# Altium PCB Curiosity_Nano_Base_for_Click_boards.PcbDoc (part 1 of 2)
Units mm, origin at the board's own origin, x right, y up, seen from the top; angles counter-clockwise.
Board outline 74.93 x 107.95 mm, 4 copper layers (Top Layer, Internal Plane 1 Gnd, Internal Plane 2 Pwr, Bottom Layer), stack 1.565 mm thick; 66 components, 59 nets, 464 pads, 89 vias.
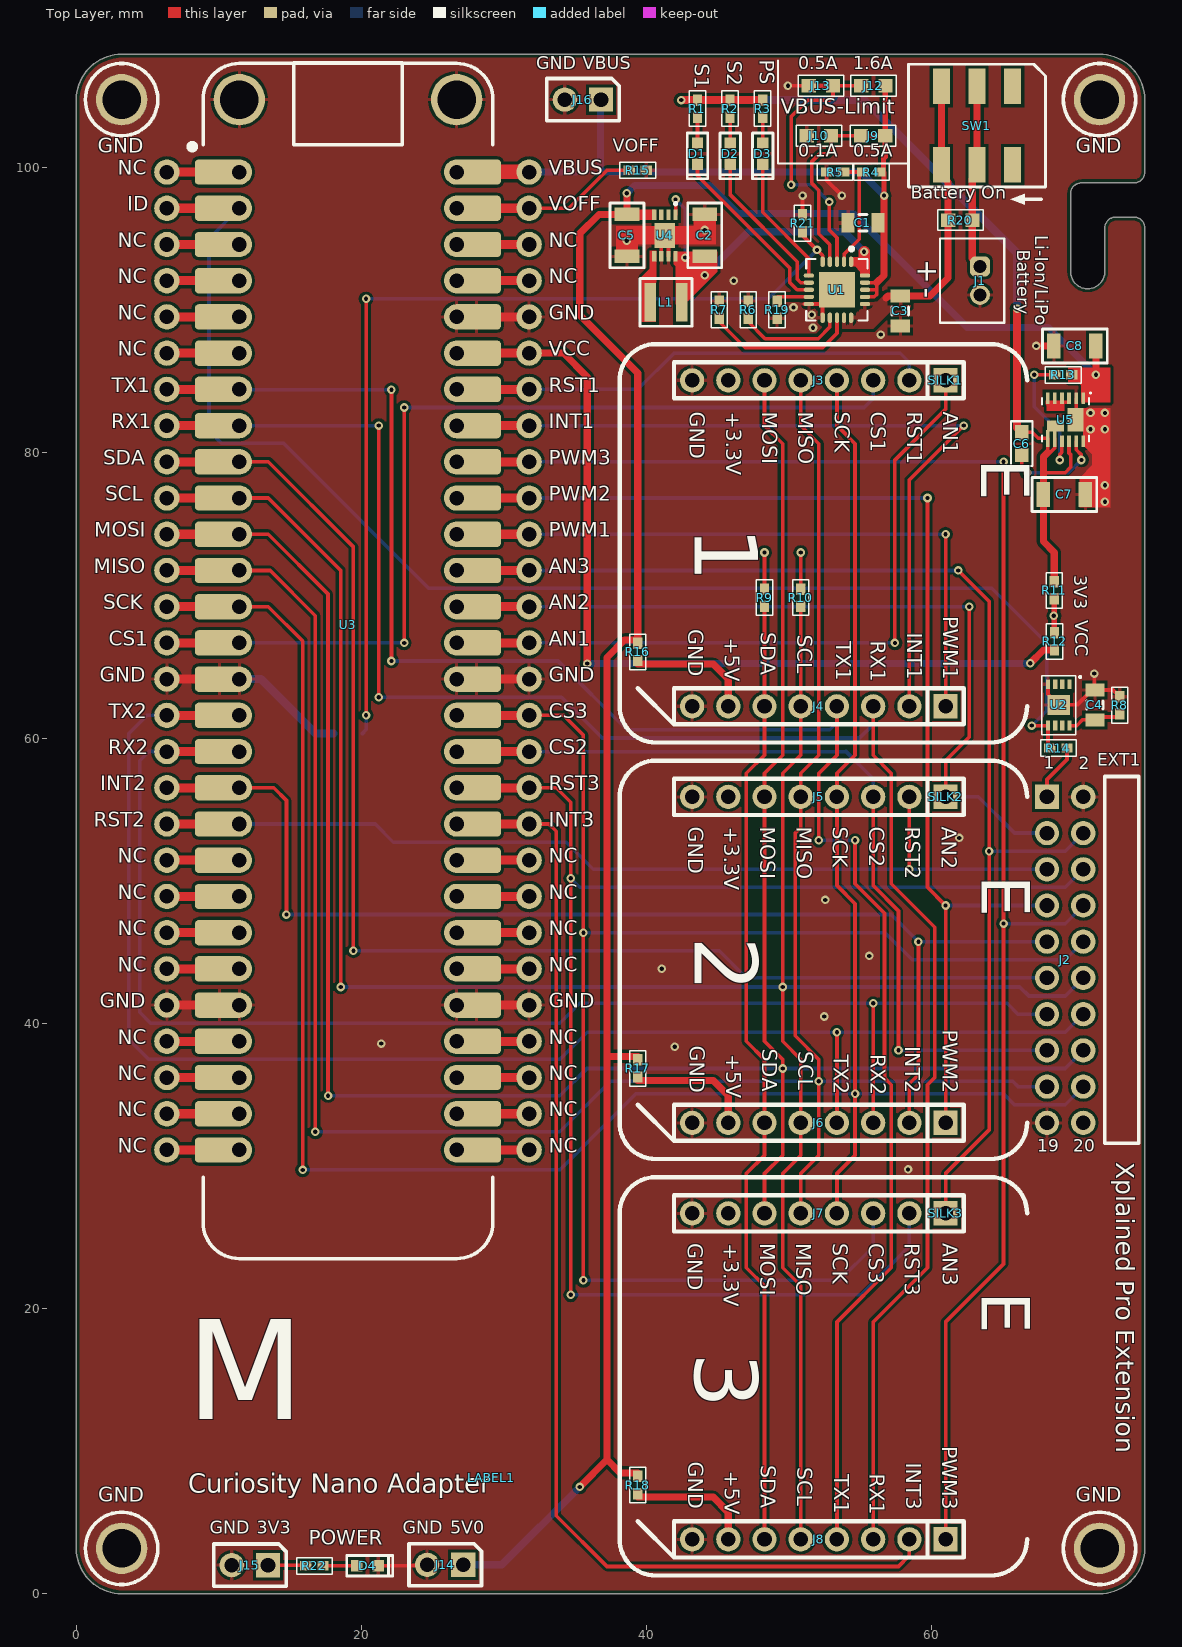
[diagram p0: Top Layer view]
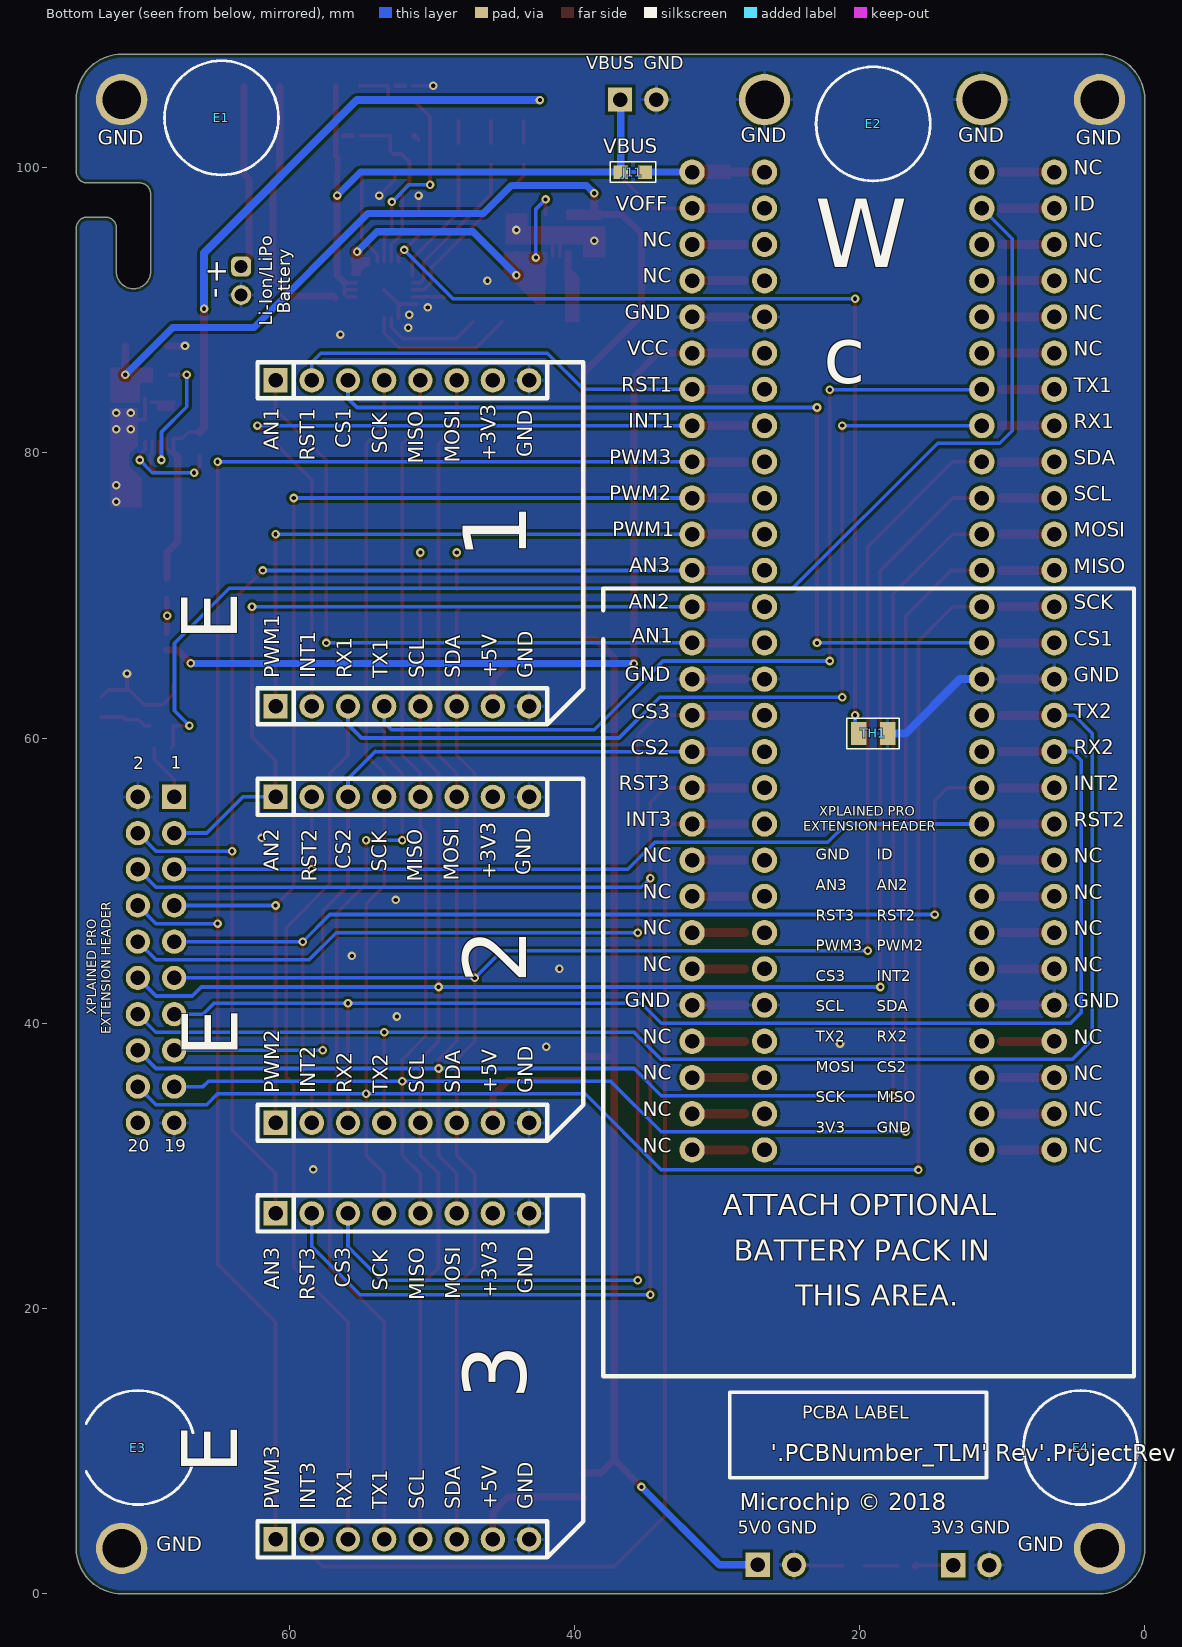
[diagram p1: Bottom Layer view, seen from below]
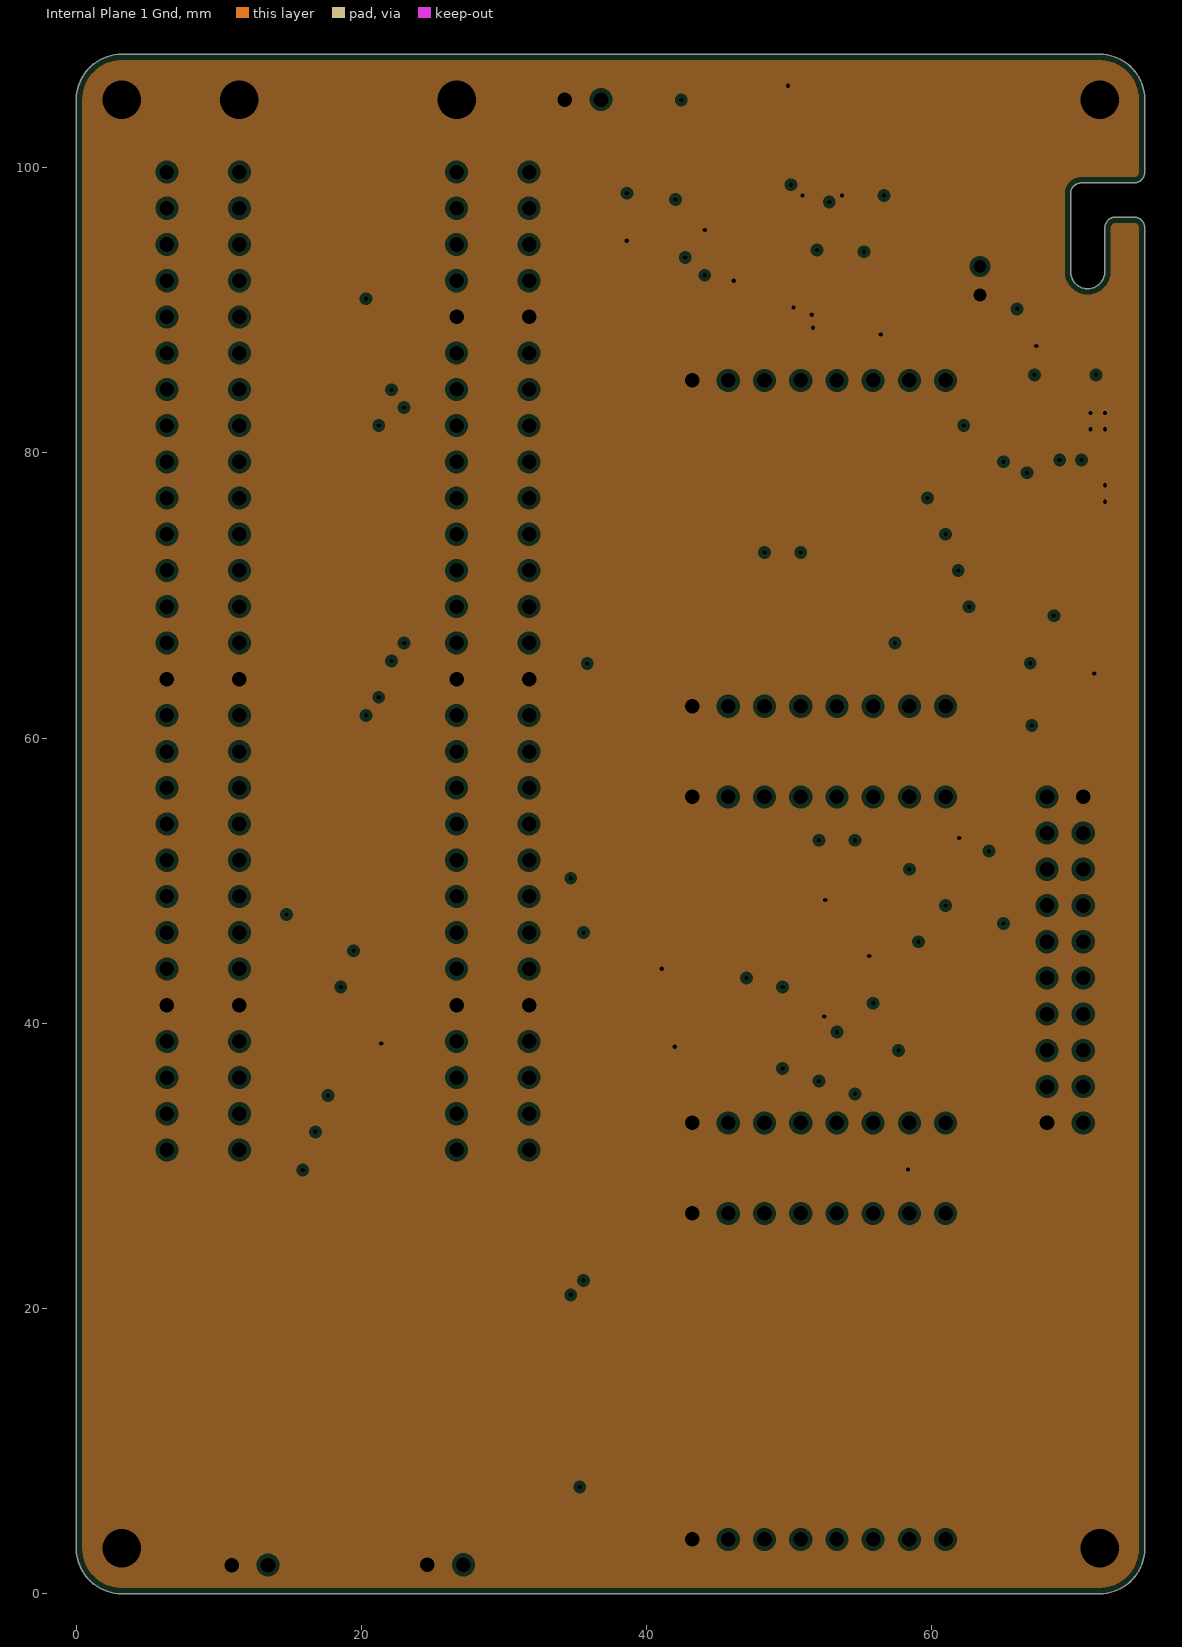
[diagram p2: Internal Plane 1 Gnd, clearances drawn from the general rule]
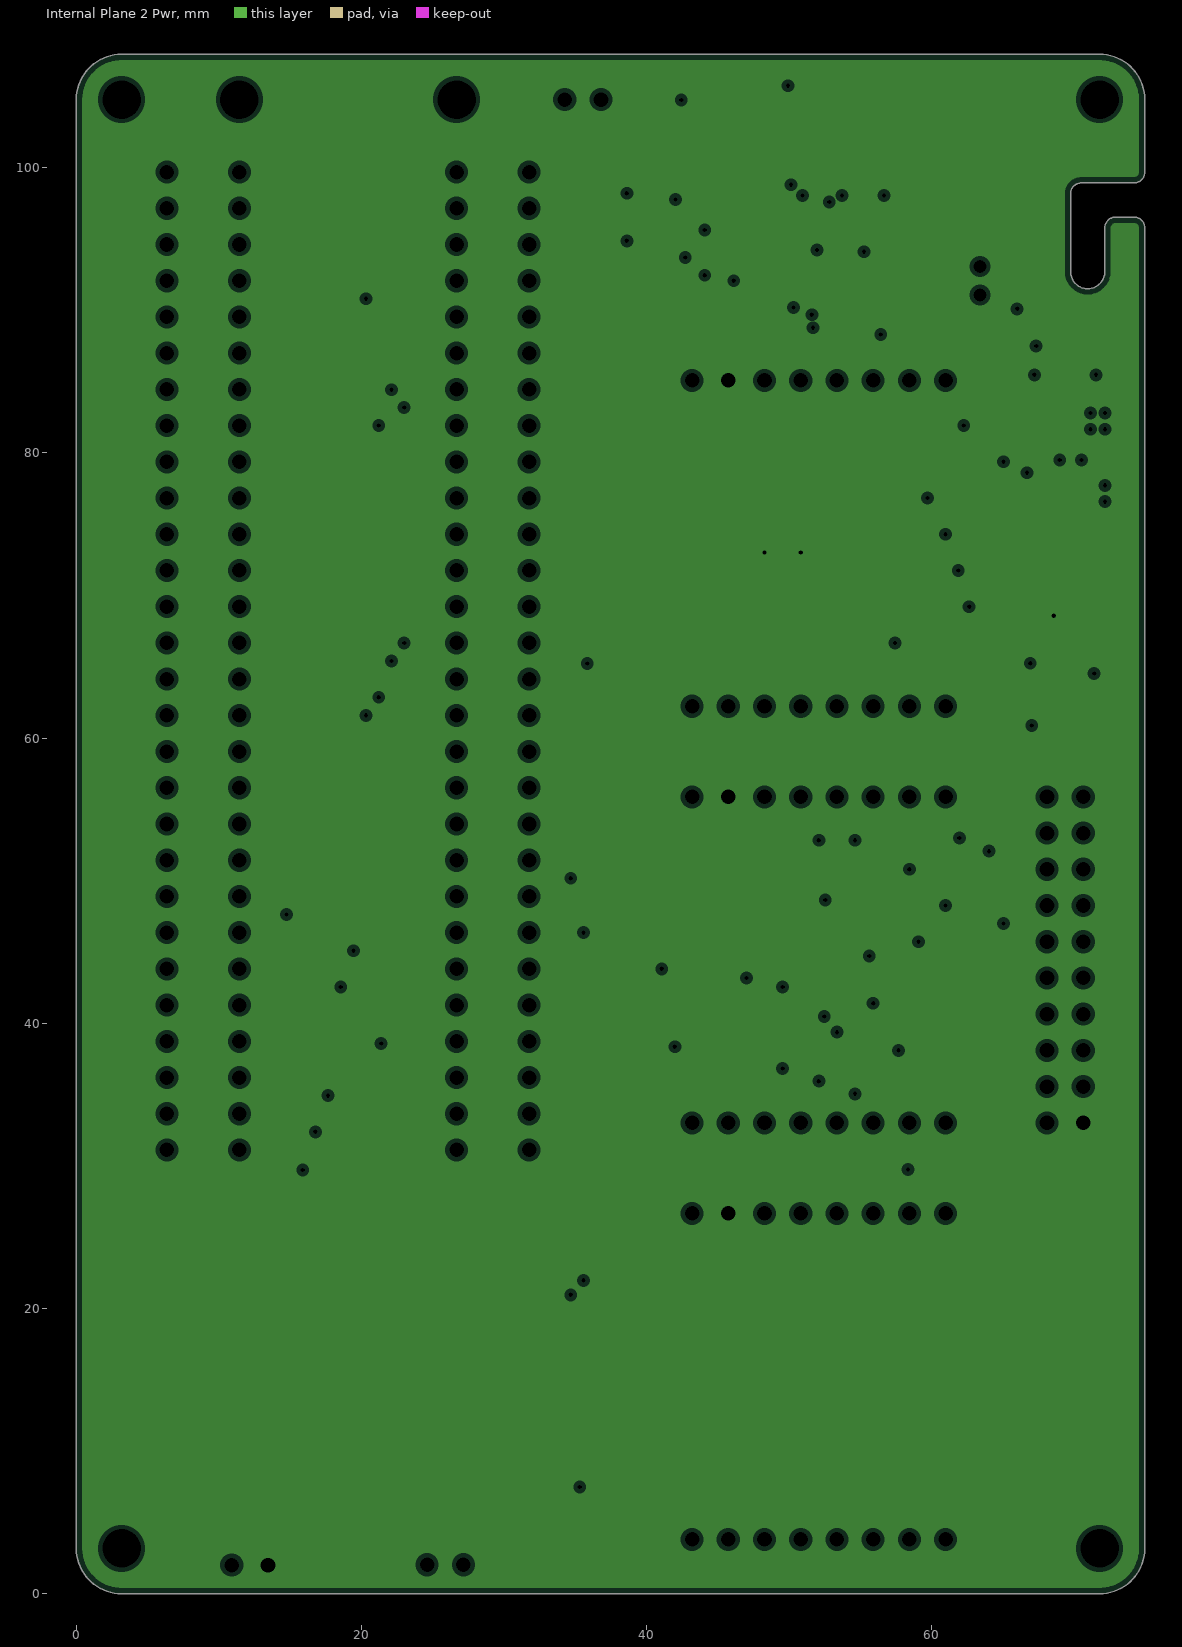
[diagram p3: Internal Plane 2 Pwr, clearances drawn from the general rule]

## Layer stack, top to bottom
Top Solder: solder mask 0.0102, Solder Resist, Dk 3.5
Top Layer: signal copper 0.0356
Dielectric 1: prepreg 0.127, FR-4, Dk 4.2
Internal Plane 1 Gnd: plane copper 0.0356, net GND
Dielectric 2: core 1.1684, Dk 4.2
Internal Plane 2 Pwr: plane copper 0.0356, net VTG_P3V3
Dielectric 3: prepreg 0.127, FR-4, Dk 4.2
Bottom Layer: signal copper 0.0356
Bottom Solder: solder mask 0.0102, Solder Resist, Dk 3.5

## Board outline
3.175,0 cw(c3.175,3.175) 0,3.175 0,104.775 cw(c3.175,104.775) 3.175,107.95 71.755,107.95 cw(c71.755,104.775) 74.93,104.775 74.93,99.695 cw(c74.168,99.695) 74.168,98.933 70.485,98.933 ccw(c70.485,98.171) 69.723,98.171 69.723,92.71 ccw(c70.923,92.71) 72.123,92.71 72.123,95.771 cw(c72.885,95.771) 72.885,96.533 74.168,96.533 cw(c74.168,95.771) 74.93,95.771 74.93,3.175 cw(c71.755,3.175) 71.755,0

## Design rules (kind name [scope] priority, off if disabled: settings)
AcuteAngle [All] p1: minimum=8.00000000000000E+0001 checktracksonly=TRUE
AssemblyTestPointUsage [All] p1: valid=2 allowmultiple=TRUE
AssemblyTestpoint AssemblyTestpoint_Bottom [OnBottomLayer and IsComponent] p1: testpointundercomponent=TRUE minsize=0.8 maxsize=2 preferedsize=0.8 minholesize=0 maxholesize=1 preferedholesize=0.25 testpointgrid=0.025 usegrid=FALSE gridtolerance=0 allowsidebottom=TRUE minspacing=1.27 compbodyclearance=1.27
AssemblyTestpoint [All] p2: testpointundercomponent=TRUE minsize=0.8 maxsize=3 preferedsize=0.8 minholesize=0 maxholesize=1.02 preferedholesize=0.25 testpointgrid=0.025 usegrid=FALSE gridtolerance=0 allowsidebottom=TRUE minspacing=1.27
BoardOutlineClearance BoardOutlineClearance_edge_connector [InComponent('J200')] p1: gap=0 ignorepadtopadclearanceinfootprint=FALSE
BoardOutlineClearance [All] p2: gap=0.25 ignorepadtopadclearanceinfootprint=FALSE
Clearance Clearance_Poly_Impedance [IsRegion vs InDifferentialPairClass('All Differential Pairs')] p1: gap=0.6 ignorepadtopadclearanceinfootprint=FALSE
Clearance Clearance_Poly [InPoly] p2: gap=0.2 ignorepadtopadclearanceinfootprint=FALSE
Clearance Clearance_same_net [All] p3: gap=0.05 ignorepadtopadclearanceinfootprint=FALSE except(0: Track-SMDPad Track-Fill SMDPad-Via SMDPad-Region SMDPad-Hole Poly-Region)
Clearance [All] p4: gap=0.2 ignorepadtopadclearanceinfootprint=FALSE
ComponentClearance ComponentClearance_BETWEEN_TESTPOINTS [InComponentClass('Testpoints') vs InComponentClass('Testpoints')] p1: gap=0 collisioncheckmode=3 verticalgap=0 showdistances=FALSE
ComponentClearance ComponentClearance_LABEL [InComponent('LABEL1')] p2: gap=0 collisioncheckmode=3 verticalgap=0 showdistances=FALSE
ComponentClearance [All] p3: gap=0 collisioncheckmode=3 verticalgap=0 showdistances=TRUE
DiffPairsRouting [All] p1: maxlimit=0.22 minlimit=0.2 mostfreqgap=0.2 toplayer_minwidth=0.18 toplayer_maxwidth=0.18 toplayer_prefwidth=0.18 bottomlayer_minwidth=0.18 bottomlayer_maxwidth=0.18 bottomlayer_prefwidth=0.18 maxuncoupledlength=20
FabricationTestPointUsage TestPointUsage [All] p1: valid=2 allowmultiple=TRUE
FabricationTestpoint Testpoint [All] p1: side=2 testpointundercomponent=TRUE minsize=0.55 maxsize=3 preferedsize=0.8 minholesize=0 maxholesize=1.02 preferedholesize=0.25 testpointgrid=0 allowsidebottom=TRUE usegrid=FALSE gridtolerance=0 minspacing=1.27
FanoutControl Fanout_Small [(CompPinCount < 5)] p1: bgadir=Out bgaviamode=Centered fanoutstyle=Auto fanoutdirection=OutThenIn viagrid=0.025 // Fanout_Small (Default Rule)
FanoutControl Fanout_Default [All] p2: bgadir=Out bgaviamode=Centered fanoutstyle=Auto fanoutdirection=Alternating viagrid=0.025 // Fanout_Default (Default Rule)
HoleSize [All] p1: absolutevalues=TRUE maxlimit=5 minlimit=0.3 maxpercent=80.000 minpercent=20.000
HoleToHoleClearance HoleToHoleClearance_NPTH [(HoleDiameter > 0) And (PadIsPlated = 'False')] p1: gap=0.25 allowstackedmicrovias=TRUE
HoleToHoleClearance [All] p2: gap=0.3 allowstackedmicrovias=TRUE
MinimumAnnularRing [All] p1: minimumring=0.15
MinimumSolderMaskSliver [All] p1: minsoldermaskwidth=0.08
NetAntennae [Not IsTestpoint] p1: netantennaetolerance=0
PlaneClearance [All] p1: clearance=0.3
PlaneConnect PlaneConnect_Special [HasPad('Free-666')] p1: planeconnectstyle=Direct reliefexpansion=0.508 reliefentries=4 reliefconductorwidth=0.254 reliefairgap=0.254
PlaneConnect [All] p2: pad.planeconnectstyle=Relief pad.reliefexpansion=0.508 pad.reliefentries=4 pad.reliefconductorwidth=0.254 pad.reliefairgap=0.254 via.planeconnectstyle=Direct via.reliefexpansion=0.508 via.reliefentries=4 via.reliefconductorwidth=0.254 via.reliefairgap=0.254
PolygonConnect PolygonConnect_Special [HasPad('Free-666') OR HasFootprint('AP8-00870')] p1: connectstyle=Direct reliefconductorwidth=0.254 reliefentries=4 polygonreliefangle="90 Angle" airgapwidth=0.254
PolygonConnect [All] p2: thpad.connectstyle=Relief thpad.reliefconductorwidth=0.254 thpad.reliefentries=4 thpad.polygonreliefangle="90 Angle" thpad.airgapwidth=0.2 smdpad.connectstyle=Relief smdpad.reliefconductorwidth=0.254 smdpad.reliefentries=4 smdpad.polygonreliefangle="90 Angle" smdpad.airgapwidth=0.2 via.connectstyle=Direct via.reliefconductorwidth=0.254 via.reliefentries=4 via.polygonreliefangle="90 Angle" via.airgapwidth=0.2
RoutingVias [All] p1: holewidth=0.25 width=0.55 viastyle="Through Hole" minholewidth=0.2 minwidth=0.5 maxholewidth=0.5 maxwidth=1
SMDNeckDown [All] p1: percent=98.000
SilkToSilkClearance SilkToSilkClearance_Text [IsText] p1: silktosilkclearance=0
SilkToSilkClearance [All] p2: silktosilkclearance=0.1
SilkToSolderMaskClearance SilkscreenOverComponentPads_Soldermask [All] p1: minsilkscreentomaskgap=0.12 clearancetoexposedcopper=FALSE
SilkToSolderMaskClearance SilkscreenOverComponentPads_Copper [All] p2: minsilkscreentomaskgap=0.2 clearancetoexposedcopper=TRUE
SolderMaskExpansion SolderMaskTenting [IsVia AND NOT (IsFabTestpoint OR IsAssyTestpoint)] p1: expansion=-1
SolderMaskExpansion [All] p2: expansion=0.06
UnRoutedNet [All] p1: checkbadconnections=TRUE
ViasUnderSMD ViasUnderSMD_GND [InPadClass('Ground_Pads')] p1: allowed=TRUE
ViasUnderSMD ViasUnderSMD_U3 [InComponent('U3')] p2: allowed=TRUE
ViasUnderSMD [All] p3: allowed=FALSE
Width Width_Power [InNetClass('Power')] p1: maxlimit=0.5 minlimit=0.254 preferedwidth=0.254
Width [All] p2: maxlimit=10 minlimit=0.254 preferedwidth=0.254
10 further rules are at their usual default settings.

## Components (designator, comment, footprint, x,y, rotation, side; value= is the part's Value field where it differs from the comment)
C1 "Generic part, no manufacturer specified." AP1-00069 55.167,96.139 r180 top value=4.7uF
C2 "" AP1-00026 44.069,95.25 r90 top value=10u
C3 "Generic part, no manufacturer specified." AP1-00069 57.785,89.954 r270 top value=4.7uF
C4 "Generic part, no manufacturer specified." AP1-00069 71.432,62.325 r90 top value=4.7uF
C5 "" AP1-00026 38.608,95.25 r270 top value=10u
C6 "" AP1-00002 66.294,80.645 r270 top value=560p
C7 "" AP1-00026 69.293,77.089 r0 top value=10u
C8 "" AP1-00026 70.026,87.503 r180 top value=10u
D1 "" AP4-00017 43.561,100.98 r90 top value="RED LED"
D2 "Farnell no. 1652078" AP4-00017 45.847,100.98 r90 top value=SML-310MTT86N
D3 "Farnell no. 1652078" AP4-00017 48.133,100.98 r90 top value=SML-310MTT86N
D4 "Farnell no. 1652078" AP4-00017 20.425,1.95 r180 top value=SML-310MTT86N
E1 "" AP8-00192 64.75,103.5 r180 bottom value=SJ-5076
E2 "" AP8-00192 19.051,103.075 r180 bottom value=SJ-5076
E3 "" AP8-00192 70.612,10.25 r180 bottom value=SJ-5076
E4 "" AP8-00192 4.5,10.25 r180 bottom value=SJ-5076
J1 "" AP8-01010 63.373,92.075 r270 top value=B2B-PH-K-S
J2 "" AP8-01078 69.342,44.45 r270 top locked value=1125-1210S0R138R1
J3 "" AP8-01081 52.07,85.09 r180 top locked value=2185-108SS0CYNP1
J4 "" AP8-01081 52.07,62.23 r180 top locked value=2185-108SS0CYNP1
J5 "" AP8-01081 52.07,55.88 r180 top locked value=2185-108SS0CYNP1
J6 "" AP8-01081 52.07,33.02 r180 top locked value=2185-108SS0CYNP1
J7 "" AP8-01081 52.07,26.67 r180 top locked value=2185-108SS0CYNP1
J8 "" AP8-01081 52.07,3.81 r180 top locked value=2185-108SS0CYNP1
J9 "" AP9-00044 55.88,102.235 r0 top net-tie value=SMD-STRAP_0603_CLOSED
J10 "" AP9-00043 52.07,102.235 r0 top value=SMD-STRAP_0603_OPEN
J11 "" AP9-00044 35.9,99.695 r0 bottom net-tie value=SMD-STRAP_0603_CLOSED
J12 "" AP9-00043 55.9,105.75 r0 top value=SMD-STRAP_0603_OPEN
J13 "" AP9-00044 52.212,105.75 r0 top net-tie value=SMD-STRAP_0603_CLOSED
J14 "" AP8-01074 25.87,2.025 r180 top value=1125-1102S0S113R1
J15 "" AP8-01074 12.17,2 r180 top value=1125-1102S0S113R1
J16 "" AP8-01074 35.525,104.775 r180 top value=1125-1102S0S113R1
L1 "" AP3-00109 41.35,90.55 r180 top value=4.7uH
LABEL1 "" AP8-00317 29.106,8.129 r180 top value="Label PCBA"
R1 "" AP2-00000 43.561,104.14 r270 top value=470R
R2 "" AP2-00000 45.847,104.14 r270 top value=470R
R3 "" AP2-00000 48.133,104.14 r270 top value=470R
R4 "" AP2-00000 55.753,99.695 r180 top value=270k
R5 "" AP2-00000 53.213,99.695 r0 top value=110k
R6 "" AP2-00000 47.117,90.043 r90 top value=10k
R7 "" AP2-00000 45.085,90.043 r90 top value=2k
R8 "" AP2-00000 73.175,62.3 r90 top value=100k
R9 "" AP2-00000 48.26,69.85 r270 top value=10k
R10 "" AP2-00000 50.8,69.85 r270 top value=10k
R11 "" AP2-00000 68.58,70.358 r90 top value=0R
R12 "" AP2-00000 68.6,66.775 r90 top value=0R
R13 "" AP2-00000 69.215,85.471 r180 top value=100k
R14 "" AP2-00000 68.875,59.3 r0 top value=0R
R15 "" AP2-00000 39.37,99.822 r0 top value=0R
R16 "" AP2-00000 39.37,66.04 r270 top value=0R
R17 "" AP2-00000 39.37,36.83 r270 top value=0R
R18 "" AP2-00000 39.37,7.62 r270 top value=0R
R19 "" AP2-00000 49.149,90.043 r270 top value=0R
R20 "" AP2-00001 62,96.329 r0 top value=0R
R21 "" AP2-00000 50.927,96.104 r90 top value=10k
R22 "" AP2-00000 16.7,1.95 r0 top value=470R
SILK1 "" AP9-00167 60.96,85.09 r270 top value=MikroBUS_socket_silkscreen_full
SILK2 "" AP9-00167 60.96,55.88 r270 top locked value=MikroBUS_socket_silkscreen_full
SILK3 "" AP9-00167 60.96,26.67 r270 top locked value=MikroBUS_socket_silkscreen_full
SW1 "" AP8-00684 63.161,102.953 r180 top value=JS202011SCQN
TH1 "" AP2-00034 20.066,60.325 r180 bottom value="NTC- B57421V2103H62"
U1 "" AP6-00165 53.34,91.44 r270 top value=MCP73871
U2 "" AP6-00409 68.892,62.325 r270 top value="ATSHA204A SWI UDFN8"
U3 "" AP8-01154 19.05,65.405 r0 top locked value=CNANO56_HOST_CONN
U4 "" AP6-00519 41.275,95.25 r270 top value=MCP1642B
U5 "" AP6-00528 69.367,82.321 r270 top value=MIC33050-SYHL

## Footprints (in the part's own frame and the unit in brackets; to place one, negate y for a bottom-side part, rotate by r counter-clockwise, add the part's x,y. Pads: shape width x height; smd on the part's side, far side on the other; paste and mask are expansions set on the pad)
AP1-00002 [mm]
  rect 1x0.95 smd: 1(-0.8,0) 2(0.8,0)
  silkscreen extent -1.58,-0.75 1.58,0.75, body extent -0.8,-0.4 0.8,0.4, height 0.3
AP1-00026 [mm]
  rect 0.95x1.75 smd: 1(-1.475,0) 2(1.475,0)
  silkscreen extent -2.27,-1.19 2.27,1.19, body extent -1.6,-0.8 1.6,0.8, height 1
AP1-00069 [mm] "0805 Cap"
  rect 0.9x1.35 smd: 1(-1.05,0) 2(1.05,0)
  silkscreen extent -0.28,-0.58 0.28,0.58, body extent -1,-0.63 1,0.63, height 0.78
AP2-00000 [mm] "Standard 0402 SMD resistor footprint"
  rect 0.8x0.65 smd: 1(-0.6,0) 2(0.6,0)
  silkscreen extent -1.25,-0.58 1.25,0.58, body extent -0.5,-0.3 0.5,0.3, height 0.2
AP2-00001 [mm]
  rect 1x0.95 smd: 1(-0.85,0) 2(0.85,0)
  silkscreen extent -1.6,-0.72 1.6,0.72, body extent -0.8,-0.4 0.8,0.4, height 0.3
AP2-00034 [mil] "0805 with Resistor 3D model, hight 0.5mm"
  rect 43x63 smd paste-39.37: 1(0,0) 2(80,0)
  silkscreen extent -32,-42 112,42, body extent 0,-25 79,25, height 24
AP3-00109 [mm] "NR301X SERIES INDUCTOR"
  rect 0.8x2.7 smd: 1(-1.1,0) 2(1.1,0)
  silkscreen extent -1.82,-1.67 1.82,1.67, body extent -1.51,-1.36 1.51,1.36, height 1.5
AP4-00017 [mm]
  rect 0.8x0.8 smd: 1(-0.75,0) 2(0.75,0)
  silkscreen extent -1.76,-0.72 1.47,0.72, body extent -0.83,-0.36 0.81,0.37, height 0.68
AP6-00165 [mm] "QFN, 20-Leads, Body 4,00x4,00mm, Pitch 0,50mm, Thermal Pad 2,70x2,70mm, IPC High Density"
  oval 0.73x0.3 smd: 1(-1.965,1) 2(-1.965,0.5) 3(-1.965,0) 4(-1.965,-0.5) 5(-1.965,-1) 11(1.965,-1) 12(1.965,-0.5) 13(1.965,0) 14(1.965,0.5) 15(1.965,1)
  oval 0.3x0.73 smd: 6(-1,-1.965) 7(-0.5,-1.965) 8(0,-1.965) 9(0.5,-1.965) 10(1,-1.965) 16(1,1.965) 17(0.5,1.965) 18(0,1.965) 19(-0.5,1.965) 20(-1,1.965)
  rect 2.5x2.5 smd: 21(0,0)
  silkscreen extent -2.99,-2.15 2.15,2.15, body extent -2,-2 2,2, height 0.9
AP6-00409 [mm]
  rect 0.7x0.3 smd mask-1: 1(-1.45,0.75) 2(-1.45,0.25) 3(-1.45,-0.25) 4(-1.45,-0.75) 5(1.45,-0.75) 6(1.45,-0.25) 7(1.45,0.25) 8(1.45,0.75)
  rect 1.4x1.6 smd paste-0.025 mask+0.075: 9(0,0)
  silkscreen extent -2.06,-1.2 2.1,1.58, body extent -1.55,-1.05 1.55,1.05, height 0.6
AP6-00519 [mm] "DFN 2mm x 3mm, 0.9mm height"
  round 0.264 on Top Paste: 0(-0.425,0.4) 0(-0.425,-0.4) 0(0,0) 0(0.425,0.4) 0(0.425,-0.4)
  rect 0.75x0.3 smd: 1(-1.45,0.75) 2(-1.45,0.25) 3(-1.45,-0.25) 4(-1.45,-0.75) 5(1.45,-0.75) 6(1.45,-0.25) 7(1.45,0.25) 8(1.45,0.75)
  rect 1.75x1.45 smd paste-0.7: 9(0,0)
  silkscreen extent -2.28,0.69 -2.17,0.81, body extent -1.5,-1 1.5,1, height 1
AP6-00528 [mm] "MLF, 12-Leads, Body 3,00x3,00mm, Pitch 0,50mm, IPC High Density"
  rect 0.8x0.26 smd: 1(-1.5,1.25) 2(-1.5,0.75) 3(-1.5,0.25) 4(-1.5,-0.25) 5(-1.5,-0.75) 6(-1.5,-1.25) 9(1.5,-0.25) 10(1.5,0.25) 11(1.5,0.75) 12(1.5,1.25)
  rect 1.2x0.26 smd: 7(1.3,-1.25) 8(1.3,-0.75)
  rect 0.775x1.2 smd: 8(0.437,-0.7)
  rect 1.65x1.125 smd paste-0.2: 13(0,0.7)
  Top Layer region: -1.325,0.375 -1.125,0.375 -1.125,-0.1 -0.65,-0.1 -0.65,-1.3 -0.988,-1.3 -1.1,-1.375 -1.325,-1.375
  silkscreen extent -1.93,-1.65 1.52,1.8, body extent -1.53,-1.53 1.53,1.53, height 0.9
AP8-00192 [mm]
  silkscreen extent -4,-4 4,4, body extent -4,-4 4,4, height 2.79
AP8-00317 [mm] "Placement area for 18x6mm sticker"
AP8-00684 [mm] "Slide Switch, C&K, 2 Pos 2 Pol"
  rect 1.2x2.5 smd: 1(-2.5,-2.75) 2(0,-2.75) 3(2.5,-2.75) 4(-2.5,2.75) 5(0,2.75) 6(2.5,2.75)
  silkscreen extent -4.8,-4.3 4.8,4.3, body extent -4.52,-3.8 4.55,3.8, height 5.5
AP8-01010 [mm] "Pin Header 1x2, 2mm THM, top entry, 100V AC/DC, 2A AC/DC (AWG #24)"
  rrect50% 1.4x1.4 hole 0.9: 1(-1,0)
  round 1.4 hole 0.9: 2(1,0)
  silkscreen extent -2.95,-2.8 2.95,1.7, body extent -2.95,-2.8 2.95,1.7, height 6
AP8-01074 [mm] "Pin header 1 x 2,  2.54mm, THM, PIP, with Pick plate"
  rect 1.7x1.7 / inner round 1.7 / far side rect 1.7x1.7 hole 1.02: 1(-1.27,0)
  round 1.7 hole 1.02: 2(1.27,0)
  silkscreen extent -2.54,-1.48 2.54,1.48, body extent -2.54,-1.27 2.54,1.27, height 8.38
AP8-01078 [mm] "2x10 Right angle 2.54mm THM, Pick plate"
  rect 2.1x2.1 on Top Paste: 0(-11.43,-1.27) 0(-11.43,1.27) 0(-8.89,-1.27) 0(-8.89,1.27) 0(-6.35,-1.27) 0(-6.35,1.27) 0(-3.81,-1.27) 0(-3.81,1.27) 0(-1.27,1.27) 0(-1.27,-1.27) 0(1.27,1.27) 0(1.27,-1.27) 0(3.81,-1.27) 0(3.81,1.27) 0(6.35,-1.27) 0(6.35,1.27) 0(8.89,-1.27) 0(8.89,1.27) 0(11.43,-1.27) 0(11.43,1.27)
  rect 1.7x1.7 / inner round 1.7 / far side rect 1.7x1.7 hole 1.02: 1(-11.43,-1.27)
  round 1.7 hole 1.02: 2(-11.43,1.27) 3(-8.89,-1.27) 4(-8.89,1.27) 5(-6.35,-1.27) 6(-6.35,1.27) 7(-3.81,-1.27) 8(-3.81,1.27) 9(-1.27,-1.27) 10(-1.27,1.27) 11(1.27,-1.27) 12(1.27,1.27) 13(3.81,-1.27) 14(3.81,1.27) 15(6.35,-1.27) 16(6.35,1.27) 17(8.89,-1.27) 18(8.89,1.27) 19(11.43,-1.27) 20(11.43,1.27)
  silkscreen extent -12.85,2.77 12.85,5.16, body extent -12.7,-1.59 12.7,11.29, height 5
AP8-01081 [mm] "1 x 8 pin female pin header, 2.54mm, PIP, Pick plate"
  rect 2.1x2.1 on Top Paste: 0(-8.89,0) 0(-6.35,0) 0(-3.81,0) 0(-1.27,0) 0(1.27,0) 0(3.81,0) 0(6.35,0) 0(8.89,0)
  rect 1.7x1.7 hole 1.02: 1(-8.89,0)
  round 1.7 hole 1.02: 2(-6.35,0) 3(-3.81,0) 4(-1.27,0) 5(1.27,0) 6(3.81,0) 7(6.35,0) 8(8.89,0)
  body extent -10.41,-1.21 10.41,1.21, height 8.51
AP8-01154 [mil] "Host Footprint with Curiosity Nano Bd Surface-Mounted"
  round 70 hole 40.16 paste-750: 1(-500,1350) 1(-300,1350) 2(-500,1250) 2(-300,1250) 3(-500,1150) 3(-300,1150) 4(-500,1050) 4(-300,1050) 5(-500,950) 5(-300,950) 6(-500,850) 6(-300,850) 7(-500,750) 7(-300,750) 8(-500,650) 8(-300,650) 9(-500,550) 9(-300,550) 10(-500,450) 10(-300,450) 11(-500,350) 11(-300,350) 12(-500,250) 12(-300,250) 13(-500,150) 13(-300,150) 14(-500,50) 14(-300,50) 15(-500,-50) 15(-300,-50) 16(-500,-150) 16(-300,-150) 17(-500,-250) 17(-300,-250) 18(-500,-350) 18(-300,-350) 19(-500,-450) 19(-300,-450) 20(-500,-550) 20(-300,-550) 21(-500,-650) 21(-300,-650) 22(-500,-750) 22(-300,-750) 23(-500,-850) 23(-300,-850) 24(-500,-950) 24(-300,-950) 25(-500,-1050) 25(-300,-1050) 26(-500,-1150) 26(-300,-1150) 27(-500,-1250) 27(-300,-1250) 28(-500,-1350) 28(-300,-1350) 29(300,-1350) 29(500,-1350) 30(300,-1250) 30(500,-1250) 31(300,-1150) 31(500,-1150) 32(300,-1050) 32(500,-1050) 33(300,-950) 33(500,-950) 34(300,-850) 34(500,-850) 35(300,-750) 35(500,-750) 36(300,-650) 36(500,-650) 37(300,-550) 37(500,-550) 38(300,-450) 38(500,-450) 39(300,-350) 39(500,-350) 40(300,-250) 40(500,-250) 41(300,-150) 41(500,-150) 42(300,-50) 42(500,-50) 43(300,50) 43(500,50) 44(300,150) 44(500,150) 45(300,250) 45(500,250) 46(300,350) 46(500,350) 47(300,450) 47(500,450) 48(300,550) 48(500,550) 49(300,650) 49(500,650) 50(300,750) 50(500,750) 51(300,850) 51(500,850) 52(300,950) 52(500,950) 53(300,1050) 53(500,1050) 54(300,1150) 54(500,1150) 55(300,1250) 55(500,1250) 56(300,1350) 56(500,1350)
  rrect30% 135x70 smd paste-70: 1(-355,1350) 2(-355,1250) 3(-355,1150) 4(-355,1050) 5(-355,950) 6(-355,850) 7(-355,750) 8(-355,650) 9(-355,550) 10(-355,450) 11(-355,350) 12(-355,250) 13(-355,150) 14(-355,50) 15(-355,-50) 16(-355,-150) 17(-355,-250) 18(-355,-350) 19(-355,-450) 20(-355,-550) 21(-355,-650) 22(-355,-750) 23(-355,-850) 24(-355,-950) 25(-355,-1050) 26(-355,-1150) 27(-355,-1250) 28(-355,-1350) 29(355,-1350) 30(355,-1250) 31(355,-1150) 32(355,-1050) 33(355,-950) 34(355,-850) 35(355,-750) 36(355,-650) 37(355,-550) 38(355,-450) 39(355,-350) 40(355,-250) 41(355,-150) 42(355,-50) 43(355,50) 44(355,150) 45(355,250) 46(355,350) 47(355,450) 48(355,550) 49(355,650) 50(355,750) 51(355,850) 52(355,950) 53(355,1050) 54(355,1150) 55(355,1250) 56(355,1350)
  round 141.73 hole 106.3: 52(-300,1550) 52(300,1550)
  Top Layer lines w25: -500,-1350 -355,-1350 ; -500,-1250 -355,-1250 ; -500,-1150 -355,-1150 ; -500,-1050 -355,-1050 ; -500,-950 -355,-950 ; -500,-850 -355,-850 ; -500,-750 -355,-750 ; -500,-650 -355,-650 ; -500,-550 -355,-550 ; -500,-450 -355,-450 ; -500,-350 -355,-350 ; -500,-250 -355,-250 ; -500,-150 -355,-150 ; -500,-50 -355,-50 ; -500,50 -355,50 ; -500,150 -355,150 ; -500,250 -355,250 ; -500,350 -355,350 ; -500,450 -355,450 ; -500,550 -355,550 ; -500,650 -355,650 ; -500,750 -355,750 ; -500,850 -355,850 ; -500,950 -355,950 ; -500,1050 -355,1050 ; -500,1150 -355,1150 ; -500,1250 -355,1250 ; -500,1350 -355,1350 ; 300,1350 355,1350 500,1350 455,1350 ; 355,-1350 500,-1350 ; 355,-1250 500,-1250 ; 355,-1150 500,-1150 ; 355,-1050 500,-1050 ; 355,-950 500,-950 ; 355,-850 500,-850 ; 355,-750 500,-750 ; 355,-650 500,-650 ; 355,-550 500,-550 ; 355,-450 500,-450 ; 355,-350 500,-350 ; 355,-250 500,-250 ; 355,-150 500,-150 ; 355,-50 500,-50 ; 355,50 500,50 ; 355,150 500,150 ; 355,250 500,250 ; 355,350 500,350 ; 355,450 500,450 ; 355,550 500,550 ; 355,650 500,650 ; 355,750 500,750 ; 355,850 500,850 ; 355,950 500,950 ; 355,1050 500,1050 ; 355,1150 500,1150 ; 355,1250 500,1250
  silkscreen extent -438,-1650 400,1650, body extent -400,-1650 400,1670, height 200
AP9-00043 [mm]
  rect 1x0.95 smd paste-1: 1(-0.85,0) 2(0.85,0)
  silkscreen extent -1.6,-0.72 1.6,0.72, body extent -0.8,-0.4 0.8,0.4, height 0.3
AP9-00044 [mm]
  rect 1x0.95 smd paste-1: 1(-0.85,0) 2(0.85,0)
  Top Layer region: -0.45,-0.15 0.45,-0.15 0.45,0.15 -0.45,0.15
  silkscreen extent -1.6,-0.72 1.6,0.72, body extent -0.8,-0.4 0.8,0.4, height 0.3
AP9-00167 [mm] "MikroBUS socket full standard silkscreen"
  silkscreen extent -2.54,-22.86 25.4,5.71

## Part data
C1 C3 C4: library part A01-0486, "Ceramic capacitor, SMD 0805, X7R, 16V, 10%,", Manufacturer="YAGEO CORP", MPN=CC0805KKX7R7BB475, TemperatureRange="-55 to +125 deg C", Tolerance=10%
C2 C5 C7 C8: library part A01-0289, "Ceramic capacitor, SMD 1206, X7R, 16V, ±10 %", Manufacturer=Murata, MPN=GRM31CR71C106KA12L, TemperatureRange="-55 - 125 deg C", Tolerance="±10 %"
C6: library part A01-0098, "Ceramic capacitor, SMD 0603, X7R, 50V, ±10 %", TemperatureRange="-55 - +125 deg C", Tolerance="50V, ±10 %"
D1: library part A10-0217, "LED, SMD 0603, Red, Wave length=620nm, 63mcd @ (20mA, 2.2Vf) rohm", Color=RED, Manufacturer=ROHM, MPN=SML-D12U1WT86, TemperatureRange="-40 to +85"
D2 D3 D4: library part A10-0056, "LED, Green, 570nm, SMD 0603", Color=GRN, Manufacturer=ROHM, MPN=SML-310MTT86N, TemperatureRange=-30
E1 E2 E3 E4: library part A08-0053, "2.8mm adhesive feet,diam 8.0mm", Manufacturer=3M, MPN=SJ-5076
J1: library part A08-2593, "Pin Header 1x2, 2mm THM, top entry, 100V AC/DC, 2A AC/DC (AWG #24)", Manufacturer="J.S.T. Mfg. Co. Ltd.", MPN=B2B-PH-K-S
J2: library part A08-2786, "Pin header, 2x10, Right Angle, 2.54mm, THM, Pin In Paste", Manufacturer="WCON HARDWARE ELECTRONICS CO., LTD", MPN=1125-1210S0R138R1
J3 J4 J5 J6 J7 J8: library part A08-2791, "1x8 receptacle pin header, 2.54mm pitch THM, PIP", Manufacturer="WCON HARDWARE ELECTRONICS CO., LTD", MPN=2185-108SS0CYNP1
J9 J11 J13: library part A09-0783, "Default closed SMD strap, 0603 size"
J10 J12: library part A09-0784, "Default open SMD strap, 0603 size"
J14 J15 J16: library part A08-2782, "1x2 pin header, 2.54mm pitch, Pin-in-Paste THM", Manufacturer="WCON HARDWARE ELECTRONICS CO., LTD", MPN=1125-1102S0S113R1, TemperatureRange="-40°C to +105°C"
L1: library part A03-0182, "4.7uH, SMT, Power inductor, 20%,  Isat = 1.04A, 3mm x 3mm x 1.5mm", Manufacturer="Taiyo Yuden", MPN=NR3015T4R7M, Tolerance=20%
LABEL1: library part A09-0611, "PCBA identification label PP Top White Gloss", Manufacturer="ACT Logimark AS", MPN=505462
R1 R2 R3 R22: library part A02-0204, "Thick film resistor, SMD 0402, 1/16W, 1%", Manufacturer=ASJ, MPN=CR10-4700-FK, TemperatureRange="-55 - +125 deg C", Tolerance="1 %"
R4: library part A02-0270, "Thick film resistor, SMD 0402, 1/16W, 1%", TemperatureRange="-55 - +125 deg C", Tolerance="1 %"
R5: library part A02-0261, "Thick film resistor, SMD 0402, 1/16W, 1%", TemperatureRange="-55� to +125�C", Tolerance="1 %"
R6 R9 R10 R21: library part A02-0236, "Thick film resistor, SMD 0402, 1/16W, 1%", Manufacturer=vishay, MPN=CRCW040210K0FKED, TemperatureRange="-55 - +125 deg C", Tolerance="1 %"
R7: library part A02-0219, "Thick film resistor, SMD 0402, 1/16W, 1%", TemperatureRange="-55 - +125 deg C", Tolerance="1 %"
R8 R13: library part A02-0260, "Thick film resistor, SMD 0402, 1/16W, 1%", Manufacturer=ASJ, MPN=CR10-1003-FK, TemperatureRange="-55� to +125�C", Tolerance="1 %"
R11 R12 R14 R15 R16 R17 R18 R19: library part A02-0163, "RES 0.0 OHM 1/16W 0402 SMD", Manufacturer=(n/a), MPN=RMCF0402ZT0R00, TemperatureRange="-55 - +125 deg C", Tolerance="1 %"
R20: library part A02-0001, "Thick film resistor, SMD 0603, 1/10W, 1%", Manufacturer=Panasonic, MPN=ERJ-3GEY0R00V, Tolerance="1 %"
SILK1 SILK2 SILK3: library part A08-2847, "Full standard silkscreen for MikroBUS socket. Derived from component files distributed by MikroElektronika. Can be deviated from in case of space requirements, etc. If so, refer to spec."
SW1: library part A08-1643, "Slide Switch, C&K, 2 Pos 2 Pol, SMD", Manufacturer="C&K Components", MPN=JS202011SCQN
TH1: library part A02-0936, "THERMISTOR NTC 10K OHM 3% 0805", Manufacturer=EPCOS, MPN=B57421V2103H62, TemperatureRange="-55C to +125C", Tolerance=+-5%
U1: library part A06-1643, "Load Sharing and Li-Ion/Li-Polymer Battery Charge Management Controller", Manufacturer="Microchip Technology Inc", MPN=MCP73871T-2CCI/ML, TemperatureRange="-40°C to  +85°C"
U2: library part A06-1276, "ATSHA204A with 1-wire interface and UDFN8 package", Manufacturer=ATMEL, MPN=ATSHA204A-MAHCZ-T
U3: library part A08-2940, "56-pin Header HOST (for CNANO solder mounting)"
U4: library part A06-1646, "1 MHz Switching Boost Regulator 5V 800mA", Manufacturer=Microchip, MPN=MCP1642BT-50I/MC, TemperatureRange="-40°C to +85°C"
U5: library part A06-1644, "3.3V Fixed, 4MHz, 600mA, Buck regulator with internal inductor with HyperLight Load", Manufacturer="Microchip Technology Inc", MPN=MIC33050-SYHL-TR, TemperatureRange="-40C to +125C"

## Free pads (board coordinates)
  round 3.6 hole 2.7: 666(3.175,3.175) 666(3.175,104.775) 666(71.755,104.775) 666(71.755,3.175)

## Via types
v1: diameter 0.6, hole 0.3, Top Layer to Bottom Layer, tented both sides, 83 vias
v2: diameter 0.6, hole 0.3, Top Layer to Bottom Layer, 6 vias

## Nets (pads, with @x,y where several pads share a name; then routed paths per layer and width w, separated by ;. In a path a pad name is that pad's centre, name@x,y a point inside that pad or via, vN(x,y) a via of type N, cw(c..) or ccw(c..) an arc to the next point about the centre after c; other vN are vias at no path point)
AN1: J3.1 U3.43 | length 45.5
  Top Layer w0.254: v1(57.404,66.675) 57.404,79.502 60.96,83.058 J3.1@60.96,85.09
  Bottom Layer w0.254: U3.43@31.75,66.675 v1(57.404,66.675)
AN2: J2.3 J5.1 U3.44 | length 53
  Top Layer w0.254: J5.1@60.96,55.88 60.96,58.42 62.611,60.071 v1(62.611,69.215)
  Bottom Layer w0.254: U3.44@31.75,69.215 v1(62.611,69.215) ; J5.1@60.96,55.88 63.246,55.88 65.786,53.34 J2.3@68.072,53.34
AN3: J2.4 J7.1 U3.45 | length 84.5
  Top Layer w0.254: J7.1@60.96,26.67 60.96,29.464 64.008,32.512 v1(64.008,52.07) 64.008,69 64.008,69.596 v1(61.849,71.755)
  Bottom Layer w0.254: U3.45@31.75,71.755 46.482,71.755 v1(61.849,71.755) ; v1(64.008,52.07) 69.342,52.07 J2.4@70.612,53.34
BAT_SW: C3.1 R20.1 SW1.3 SW1.6 U1.14 U1.15 U1.16 | length 18.5
  Top Layer w0.5: 56.793,90.875 56.922,91.004 C3.1@57.785,91.004 59.873,91.004 61.126,92.257 61.126,97.282 61.126,98.988 60.661,99.453 SW1.6@60.661,100.203 SW1.3@60.661,105.703
BATTERY: J1.1 R20.2 SW1.2 SW1.5 | length 13
  Top Layer w0.5: SW1.2@63.161,105.703 SW1.5@63.161,100.203 63.161,99.523 62.826,99.188 62.826,97.282 62.826,93.622 J1.1@63.373,93.075
CS1: J3.3 U3.14 | length 62.5
  Top Layer w0.254: v1(22.987,66.675) v1(22.987,83.185)
  Bottom Layer w0.254: U3.14@11.43,66.675 v1(22.987,66.675) ; v1(22.987,83.185) 55.245,83.185 55.88,83.82 J3.3@55.88,85.09
CS2: J2.15 J5.3 U3.40 | length 55.1
  Top Layer w0.254: J5.3@55.88,55.88 55.88,49.657 57.658,47.879 v1(57.658,38.1)
  Bottom Layer w0.254: U3.40@31.75,59.055 53.975,59.055 55.88,57.15 J5.3@55.88,55.88 ; v1(57.658,38.1) J2.15@68.072,38.1
CS3: J2.10 J7.3 U3.41 | length 102.6
  Top Layer w0.254: U3.41@31.75,61.595 34.163,61.595 35.56,60.198 v1(35.56,46.355) v1(35.56,21.971)
  Bottom Layer w0.254: v1(35.56,21.971) 53.525,21.971 55.88,24.326 J7.3@55.88,26.67 ; v1(35.56,46.355) 56.71,46.355 58.615,44.45 69.342,44.45 J2.10@70.612,45.72
GND: C1.2 C2.2 C3.2 C4.2 C5.2 C7.2 C8.2 D4.1 J1.2 J2.2 J2.19 J3.8 J4.8 J5.8 J6.8 J7.8 J8.8 J10.1 J13.1 J14.2 J15.2 J16.2 pad.666 R5.1 R6.2 R7.2 R8.2 R15.2 R19.2 R21.2 TH1.2 U1.10 U1.11 U1.21 U2.4 U2.9 U3.15 U3.24 U3.33 U3.42 U3.52 U4.6 U4.7 U4.9 U5.2 U5.12 U5.13 | length 35.3
  Top Layer w0.254: D4.1@21.175,1.95 24.525,1.95 J14.2@24.6,2.025 ; U4.6@41.025,93.8 U4.9@41.025,95 ; U4.7@41.525,93.8 U4.9@41.525,95 ; v1(49.9,105.75) J13.1@51.362,105.75 ; R21.2@50.927,96.704 v1(50.927,98.044) ; J10.1@50.927,101.942 J10.1@51.22,102.235 ; R5.1@52.613,99.695 52.613,99.123 v1(53.692,98.044) ; U2.4@68.142,63.775 68.142,63.075 U2.9@68.892,62.325 70.175,62.325 71.225,63.375 C4.2@71.432,63.375 ; U5.13@70.062,82.32 U5.13@70.112,82.37 ; U5.2@70.117,83.821 70.117,82.371 U5.13@70.067,82.321 70.637,82.321 v1(71.12,82.804) ; v1(71.375,64.525) 71.375,63.432 C4.2@71.432,63.375 ; R8.2@73.175,62.9 72.7,63.375 C4.2@71.432,63.375
  Top Layer w0.279: U1.10@51.07,90.44 U1.10@51.375,90.44 U1.21@52.34,90.44 ; U1.11@52.34,89.475 U1.21@52.34,90.44 ; U1.21@53.34,91.44 U1.21@52.34,90.44
  Top Layer w0.305: U4.9@41.025,95 U4.9@41.275,95.25
  Top Layer w0.508: v1(67.31,87.503) C8.2@68.551,87.503
  Bottom Layer w0.559: U3.15@11.43,64.135 12.954,64.135 16.764,60.325 TH1.2@18.034,60.325
  other v1: 58.325,29.75 41.975,38.35 21.375,38.575 52.45,40.475 41.05,43.815 55.606,44.725 52.525,48.65 61.925,53 72.136,76.581 72.136,77.724 71.12,81.661 72.136,81.661 72.136,82.804 56.41,88.3 51.661,88.777 51.583,89.69 50.293,90.2 46.101,92.075 38.608,94.869 44.069,95.631
ID: R14.1 U2.5 U3.2 | length 90.4
  Top Layer w0.254: v2(67,60.875) U2.5@68.142,60.875 68.142,59.433 R14.1@68.275,59.3
  Bottom Layer w0.254: U3.2@11.43,97.155 9.3,95.025 9.3,81.55 10.175,80.675 14.525,80.675 24.7,70.5 64.2,70.5 68.05,66.65 68.05,61.925 v2(67,60.875)
ID_XPRO: J2.1 R14.2 | length 4
  Top Layer w0.254: J2.1@68.072,55.88 68.072,57.097 69.475,58.5 R14.2@69.475,59.3
INT1: J4.2 U3.49 | length 51.7
  Top Layer w0.254: J4.2@58.42,62.23 58.42,78.105 v1(62.23,81.915)
  Bottom Layer w0.254: U3.49@31.75,81.915 v1(62.23,81.915)
INT2: J2.9 J6.2 U3.18 | length 78.8
  Top Layer w0.254: U3.18@11.43,56.515 13.843,56.515 14.736,55.622 v1(14.736,47.625) ; J6.2@58.42,33.02 58.42,35.763 59.055,36.398 v1(59.055,45.72)
  Bottom Layer w0.254: v1(14.736,47.625) 44.069,47.625 57.15,47.625 v1(59.055,45.72) J2.9@68.072,45.72
INT3: J8.2 U3.38 | length 77.8
  Top Layer w0.254: U3.38@31.75,53.975 33.147,53.975 33.65,53.472 33.65,5.466 37.211,1.905 57.658,1.905 58.42,2.667 J8.2@58.42,3.81
MISO: J2.17 J3.5 J5.5 J7.5 U3.12 | length 156.6
  Top Layer w0.254: U3.12@11.43,71.755 13.589,71.755 16.764,68.58 16.764,67.183 16.764,37.465 v1(16.764,32.385) ; J7.5@50.8,26.67 50.8,29.464 52.07,30.734 v1(52.07,35.941) 52.07,37.465 50.419,39.116 50.419,53.34 50.8,53.721 J5.5@50.8,55.88 50.8,57.531 52.07,58.801 52.07,80.645 50.8,81.915 J3.5@50.8,85.09
  Bottom Layer w0.254: v1(16.764,32.385) 33.909,32.385 37.465,35.941 v1(52.07,35.941) 65.659,35.941 66.04,35.56 J2.17@68.072,35.56
MOSI: J2.16 J3.6 J5.6 J7.6 U3.11 | length 157.9
  Top Layer w0.254: U3.11@11.43,74.295 13.462,74.295 17.653,70.104 v1(17.653,34.925) ; J7.6@48.26,26.67 48.26,29.464 49.53,30.734 v1(49.53,36.83) 49.53,37.465 48.26,38.735 J5.6@48.26,55.88 48.26,57.531 49.53,58.801 49.53,80.645 48.26,81.915 J3.6@48.26,85.09
  Bottom Layer w0.254: v1(17.653,34.925) 33.909,34.925 35.814,36.83 v1(49.53,36.83) 69.342,36.83 J2.16@70.612,38.1
NetC4_1: C4.1 R8.1 U2.8 | length 3.7
  Top Layer w0.254: U2.8@69.781,60.875 70.151,60.875 70.551,61.275 C4.1@71.432,61.275 71.632,61.475 R8.1@73.225,61.475
NetC6_2: C6.2 U5.11 | length 7
  Top Layer w0.254: C6.2@66.294,79.845 66.294,78.994 v1(66.675,78.613) ; U5.11@70.112,80.82 70.112,80.231 70.485,79.858 v1(70.485,79.502)
  Bottom Layer w0.254: v1(66.675,78.613) 69.596,78.613 v1(70.485,79.502)
NetD1_2: D1.2 R1.2 | length 1.6
  Top Layer w0.254: D1.2@43.561,101.73 R1.2@43.561,103.29
NetD2_2: D2.2 R2.2 | length 1.6
  Top Layer w0.254: D2.2@45.847,101.73 R2.2@45.847,103.29
NetD3_2: D3.2 R3.2 | length 1.6
  Top Layer w0.254: D3.2@48.133,101.73 R3.2@48.133,103.29
NetD4_2: D4.2 R22.2 | length 2.4
  Top Layer w0.254: R22.2@17.3,1.95 D4.2@19.675,1.95
NetJ4_7: J4.7 R16.2 | length 8.7
  Top Layer w0.5: R16.2@39.37,65.19 44.665,65.19 45.72,64.135 J4.7@45.72,62.23
NetJ6_7: J6.7 R17.2 | length 8.7
  Top Layer w0.5: R17.2@39.37,35.98 44.665,35.98 45.72,34.925 J6.7@45.72,33.02
NetJ8_7: J8.7 R18.2 | length 8.7
  Top Layer w0.5: R18.2@39.37,6.77 44.665,6.77 45.72,5.715 J8.7@45.72,3.81
NetL1_2: L1.2 U4.5
NetR13_2: R13.2 U5.9 | length 9.3
  Top Layer w0.254: v1(67.183,85.471) R13.2@68.365,85.471 ; v1(68.961,79.502) 68.961,79.883 69.112,80.034 U5.9@69.112,80.82
  Bottom Layer w0.254: v1(67.183,85.471) 67.183,83.236 68.961,81.458 v1(68.961,79.502)
NetU5_3: U5.3 U5.4 U5.5 U5.6
P\G\: D3.1 U1.6 | length 9.1
  Top Layer w0.254: D3.1@48.133,100.23 48.133,96.866 51.375,93.624 U1.6@51.375,92.44
PROG1: R7.1 U1.13 | length 10.5
  Top Layer w0.254: R7.1@45.085,89.193 46.902,87.376 52.324,87.376 53.34,88.392 U1.13@53.34,89.475
PROG2: J9.1 J10.2 U1.4 | length 12.4
  Top Layer w0.254: U1.4@52.84,93.405 52.84,94.607 52.07,95.377 52.07,98.425 51.562,98.933 51.562,100.399 52.12,100.957 52.697,100.957 52.92,101.18 J10.2@52.92,102.235 J9.1@55.03,102.235
PROG3: R6.1 U1.12 | length 7.2
  Top Layer w0.254: R6.1@47.117,89.193 48.299,88.011 52.019,88.011 52.84,88.832 U1.12@52.84,89.475
PWM1: J4.1 U3.46 | length 41.3
  Top Layer w0.254: J4.1@60.96,62.23 v1(60.96,74.295)
  Bottom Layer w0.254: U3.46@31.75,74.295 v1(60.96,74.295)
PWM2: J2.7 J6.1 U3.47 | length 79.4
  Top Layer w0.254: v1(59.69,76.835) 59.69,49.53 v1(60.96,48.26) J6.1@60.96,33.02
  Bottom Layer w0.254: U3.47@31.75,76.835 v1(59.69,76.835) ; v1(60.96,48.26) J2.7@68.072,48.26
PWM3: J2.8 J8.1 U3.48 | length 116.6
  Top Layer w0.254: J8.1@60.96,3.81 60.96,19.05 65.024,23.114 v1(65.024,46.99) 65.024,47.625 v1(65.024,79.375)
  Bottom Layer w0.254: U3.48@31.75,79.375 v1(65.024,79.375) ; v1(65.024,46.99) 69.342,46.99 J2.8@70.612,48.26
RST1: J3.2 U3.50 | length 29.3
  Bottom Layer w0.254: U3.50@31.75,84.455 39.37,84.455 41.91,86.995 57.785,86.995 58.42,86.36 J3.2@58.42,85.09
RST2: J2.5 J5.2 U3.19 | length 63
  Top Layer w0.254: v1(58.42,50.8) J5.2@58.42,55.88
  Bottom Layer w0.254: U3.19@11.43,53.975 20.955,53.975 22.225,52.705 34.35,52.705 36.255,50.8 v1(58.42,50.8) J2.5@68.072,50.8
RST3: J2.6 J7.2 U3.39 | length 102.1
  Top Layer w0.254: U3.39@31.75,56.515 33.655,56.515 34.671,55.499 v1(34.671,50.165) v1(34.671,20.955)
  Bottom Layer w0.254: v1(34.671,20.955) 55.025,20.955 58.42,24.35 J7.2@58.42,26.67 ; v1(34.671,50.165) 35.306,49.53 69.342,49.53 J2.6@70.612,50.8
RX1: J4.3 J8.3 U3.8 | length 128.3
  Top Layer w0.254: v1(21.209,62.865) v1(21.209,81.915) ; J8.3@55.88,3.81 55.88,19.05 59.69,22.86 59.69,35.687 60.198,36.195 60.198,46.736 57.15,49.784 57.15,57.523 55.88,58.793 J4.3@55.88,62.23
  Bottom Layer w0.254: U3.8@11.43,81.915 v1(21.209,81.915) ; v1(21.209,62.865) 34.018,62.865 36.877,60.006 54.926,60.006 55.88,60.96 J4.3@55.88,62.23
RX2: J2.13 J6.3 U3.17 | length 93
  Top Layer w0.254: J6.3@55.88,33.02 v1(55.88,41.402)
  Bottom Layer w0.254: U3.17@6.35,59.055 5.08,59.055 4.445,58.42 4.445,40.767 5.207,40.005 33.909,40.005 35.306,41.402 v1(55.88,41.402) 65.278,41.402 66.04,40.64 J2.13@68.072,40.64
SCK: J2.18 J3.4 J5.4 J7.4 U3.13 | length 160.8
  Top Layer w0.254: U3.13@11.43,69.215 13.462,69.215 15.875,66.802 15.875,65.405 15.875,34.925 v1(15.875,29.718) ; J7.4@53.34,26.67 53.34,29.464 54.61,30.734 v1(54.61,35.052) 54.61,48.387 53.34,49.657 J5.4@53.34,55.88 53.34,57.531 54.61,58.801 54.61,80.645 53.34,81.915 J3.4@53.34,85.09
  Bottom Layer w0.254: v1(15.875,29.718) 33.909,29.718 39.243,35.052 v1(54.61,35.052) 65.024,35.052 65.786,34.29 69.342,34.29 J2.18@70.612,35.56
SCL: J2.12 J4.5 J6.5 J8.5 R10.2 U3.10 | length 158.6
  Top Layer w0.254: U3.10@11.43,76.835 13.462,76.835 18.542,71.755 v1(18.542,42.545) ; J8.5@50.8,3.81 50.8,21.59 49.53,22.86 49.53,29.464 50.8,30.734 J6.5@50.8,33.02 50.8,37.465 49.53,38.735 49.53,57.541 50.8,58.811 J4.5@50.8,62.23 R10.2@50.8,69
  Bottom Layer w0.254: v1(18.542,42.545) 34.55,42.545 36.675,42.545 v1(49.53,42.545) 66.167,42.545 66.802,41.91 69.342,41.91 J2.12@70.612,43.18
